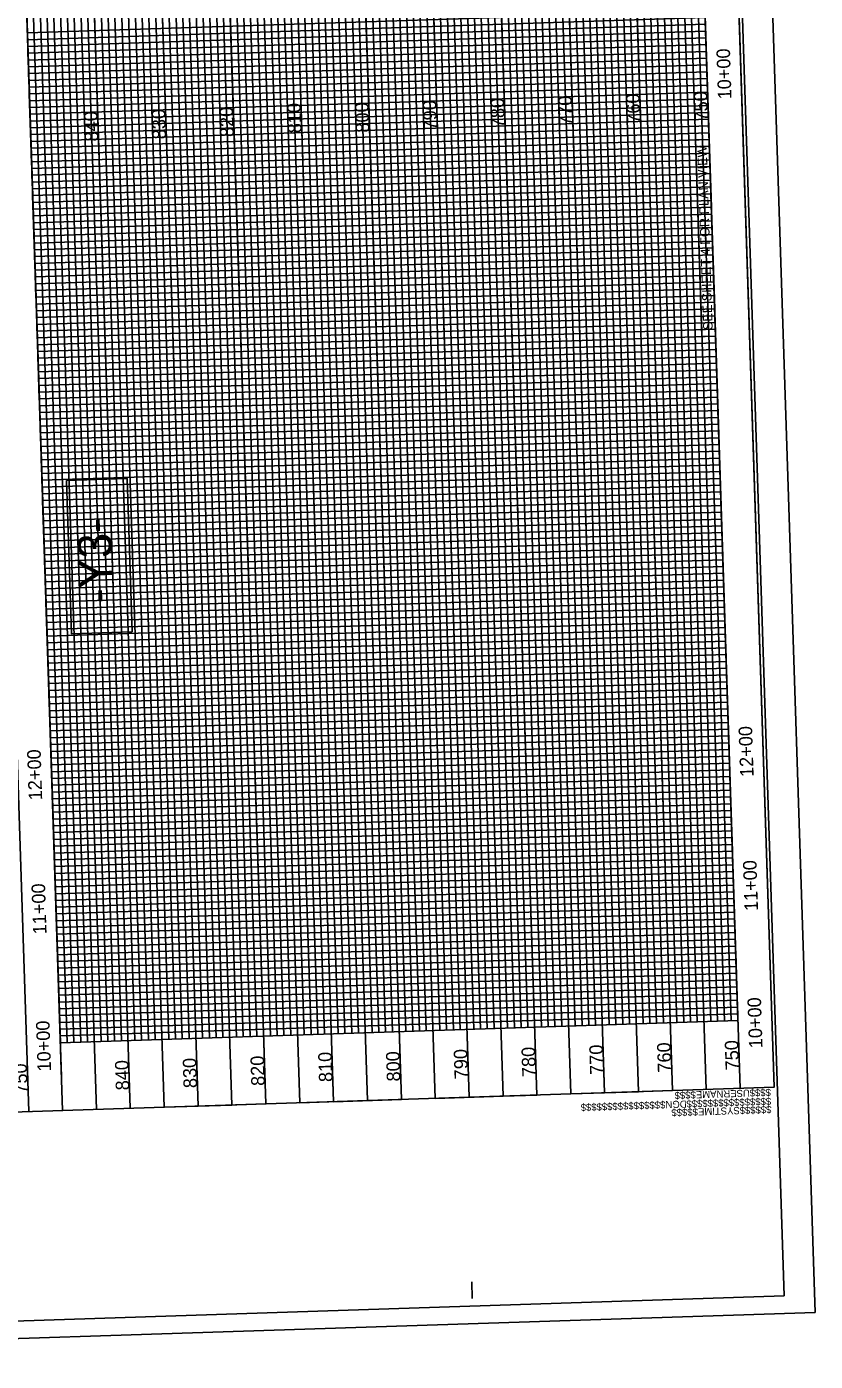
# Model space of a CAD drawing. Extents: x 1627314 to 1628469, y 762309 to 764230.
# Drawn here: x 1627888 to 1628469, y 762309 to 763293 of the extents above; entities that cross this region are included whole.
import ezdxf

# ---------------------------------------------------------------- set-up
doc = ezdxf.new("R2010")
doc.units = 0
for name, color, linetype in [('Exist Vertical Profile Horizontal Axis Label Major', 7, 'Continuous'), ('Exist Vertical Profile Vertical Axis Label', 7, 'Continuous'), ('Prop DSN Text', 7, 'Continuous'), ('Prop Grid Mask', 7, 'Continuous'), ('Sheet Data Field CELL', 7, 'Continuous'), ('Sheet DOT Grid CELL', 7, 'Continuous'), ('Sheet Layout Profile Border Port 2', 7, 'Continuous'), ('Sheet Plot Border Inside CELL', 7, 'Continuous'), ('Sheet Plot Border Outside CELL', 7, 'Continuous'), ('Sheet Profile CELL', 7, 'Continuous'), ('Sheet Profile Grid Major CELL', 7, 'Continuous'), ('Sheet Profile Grid Middle CELL', 7, 'Continuous'), ('Sheet Profile Grid Minor CELL', 7, 'Continuous')]:
    doc.layers.add(name, color=color, linetype=linetype)

msp = doc.modelspace()

# ---------------------------------------------------------------- linework, layer by layer
at = {"layer": 'Prop Grid Mask'}
for points in [[(1627891.16, 763193.83), (1627889.52, 763243.8), (1628389.25, 763260.15), (1628390.89, 763210.18)], [(1628380.89, 763209.85), (1628385.63, 763064.93), (1628395.63, 763065.25), (1628390.89, 763210.18)], [(1627965.43, 762847.15), (1627961.73, 762960.18), (1627917.01, 762958.71), (1627920.71, 762845.69)]]:
    msp.add_lwpolyline(points, close=True, dxfattribs=at)
at = {"layer": 'Sheet DOT Grid CELL'}
for p, q in [((1628163.91, 762502.38), (1628114.87, 764001.46)), ((1628213.88, 762504.01), (1628164.85, 764003.1)), ((1628263.85, 762505.65), (1628214.82, 764004.73)), ((1628313.83, 762507.28), (1628264.79, 764006.37)), ((1628363.8, 762508.92), (1628314.77, 764008)), ((1627914.04, 762494.2), (1627865.01, 763993.29)), ((1627964.01, 762495.84), (1627914.98, 763994.92)), ((1628013.99, 762497.47), (1627964.95, 763996.56)), ((1628063.96, 762499.11), (1628014.93, 763998.19)), ((1628113.93, 762500.74), (1628064.9, 763999.83)), ((1627889.52, 763243.8), (1628389.25, 763260.15)), ((1627891.16, 763193.83), (1628390.89, 763210.18)), ((1627892.79, 763143.86), (1628392.52, 763160.2)), ((1627894.43, 763093.88), (1628394.16, 763110.23)), ((1627896.06, 763043.91), (1628395.79, 763060.26)), ((1627897.69, 762993.94), (1628397.43, 763010.28)), ((1627899.33, 762943.96), (1628399.06, 762960.31)), ((1627900.96, 762893.99), (1628400.7, 762910.34)), ((1627902.6, 762844.02), (1628402.33, 762860.36)), ((1627904.23, 762794.04), (1628403.97, 762810.39)), ((1627905.87, 762744.07), (1628405.6, 762760.42)), ((1627907.5, 762694.1), (1628407.24, 762710.44)), ((1627909.14, 762644.12), (1628408.87, 762660.47)), ((1627910.77, 762594.15), (1628410.5, 762610.5)), ((1627912.41, 762544.18), (1628412.14, 762560.52))]:
    msp.add_line(p, q, dxfattribs=at)
at = {"layer": 'Sheet Layout Profile Border Port 2'}
msp.add_lwpolyline([(1627912.41, 762544.18), (1627866.64, 763943.43), (1628366.37, 763959.78), (1628412.14, 762560.52)], close=True, dxfattribs=at)
at = {"layer": 'Sheet Plot Border Inside CELL'}
msp.add_lwpolyline([(1628446.34, 762357.53), (1628391.86, 764023.14), (1627337.33, 763988.65), (1627391.81, 762323.04)], close=True, dxfattribs=at)
at = {"layer": 'Sheet Plot Border Outside CELL'}
msp.add_lwpolyline([(1628469.21, 762345.27), (1628413.63, 764044.37), (1627314.22, 764008.4), (1627369.79, 762309.31)], close=True, dxfattribs=at)
at = {"layer": 'Sheet Profile CELL'}
for p, q in [((1628364.74, 764009.75), (1628413.77, 762510.55)), ((1628438.76, 762511.37), (1628389.72, 764010.57)), ((1627889.05, 762493.39), (1627840.02, 763992.59)), ((1627914.04, 762494.2), (1627865, 763993.4)), ((1628438.76, 762511.37), (1628438.76, 762511.37)), ((1628438.76, 762511.37), (1628438.76, 762511.37)), ((1628438.76, 762511.37), (1628438.76, 762511.37)), ((1628438.76, 762511.37), (1628438.76, 762511.37)), ((1628438.76, 762511.37), (1628438.76, 762511.37)), ((1628438.76, 762511.37), (1628438.76, 762511.37)), ((1628438.76, 762511.37), (1628438.76, 762511.37)), ((1628216.24, 762355.51), (1628215.83, 762368))]:
    msp.add_line(p, q, dxfattribs=at)
msp.add_lwpolyline([(1627340.28, 763976.24), (1627389.32, 762477.04), (1628438.76, 762511.37), (1628389.72, 764010.57)], close=True, dxfattribs=at)
msp.add_lwpolyline([(1628437.53, 762548.85), (1628437.53, 762548.85)], dxfattribs=at)
at = {"layer": 'Sheet Profile Grid Major CELL'}
for p, q in [((1627891.16, 763193.83), (1627889.52, 763243.8)), ((1627894.43, 763093.88), (1627892.79, 763143.86)), ((1627897.69, 762993.94), (1627896.06, 763043.91)), ((1628413.77, 762510.55), (1628413.77, 762510.55))]:
    msp.add_line(p, q, dxfattribs=at)
for points in [[(1628064.9, 763999.94), (1628113.93, 762500.74), (1628163.91, 762502.38), (1628114.87, 764001.58)], [(1628164.84, 764003.21), (1628213.88, 762504.01), (1628263.85, 762505.65), (1628214.82, 764004.85)], [(1628264.79, 764006.48), (1628313.83, 762507.28), (1628313.83, 762507.28), (1628363.8, 762508.92), (1628314.76, 764008.11)], [(1628364.74, 764009.75), (1628413.77, 762510.55)], [(1627914.98, 763995.04), (1627964.01, 762495.84)], [(1627964.95, 763996.67), (1628013.99, 762497.47), (1628063.96, 762499.11), (1628014.92, 763998.31)], [(1627912.41, 762544.18), (1628412.14, 762560.52), (1628410.5, 762610.5), (1627910.77, 762594.15), (1627909.14, 762644.12), (1628408.87, 762660.47), (1628407.24, 762710.44), (1627907.5, 762694.1), (1627905.87, 762744.07), (1628405.6, 762760.42), (1628403.97, 762810.39), (1627904.23, 762794.04), (1627902.6, 762844.02), (1628402.33, 762860.36), (1628400.7, 762910.34), (1627900.96, 762893.99), (1627899.33, 762943.96), (1628399.06, 762960.31), (1628397.43, 763010.28), (1627897.69, 762993.94), (1627896.06, 763043.91), (1628395.79, 763060.26), (1628394.16, 763110.23), (1627894.43, 763093.88), (1627892.79, 763143.86), (1628392.52, 763160.2), (1628390.89, 763210.18), (1627891.16, 763193.83), (1627889.52, 763243.8), (1628389.25, 763260.15), (1628387.62, 763310.12)]]:
    msp.add_lwpolyline(points, dxfattribs=at)
at = {"layer": 'Sheet Profile Grid Middle CELL'}
for points in [[(1628139.86, 764002.39), (1628188.89, 762503.2), (1628238.87, 762504.83), (1628189.83, 764004.03)], [(1628239.8, 764005.66), (1628288.84, 762506.46), (1628338.81, 762508.1), (1628289.78, 764007.3)], [(1628339.75, 764008.93), (1628388.79, 762509.73)], [(1627939.03, 762495.02), (1627889.99, 763994.22)], [(1627939.96, 763995.85), (1627989, 762496.66), (1628038.97, 762498.29), (1627989.94, 763997.49)], [(1628039.91, 763999.12), (1628088.95, 762499.93), (1628138.92, 762501.56), (1628089.88, 764000.76)], [(1627913.22, 762519.19), (1627911.59, 762569.16), (1628411.32, 762585.51), (1628409.69, 762635.48), (1627909.95, 762619.14), (1627908.32, 762669.11), (1628408.05, 762685.46), (1628406.42, 762735.43), (1627906.69, 762719.08), (1627905.05, 762769.06), (1628404.78, 762785.4), (1628403.15, 762835.38), (1627903.42, 762819.03), (1627901.78, 762869), (1628401.51, 762885.35), (1628399.88, 762935.32), (1627900.15, 762918.98), (1627898.51, 762968.95), (1628398.24, 762985.3), (1628396.61, 763035.27), (1627896.88, 763018.92), (1627895.24, 763068.9), (1628394.98, 763085.24), (1628393.34, 763135.22), (1628393.34, 763135.22), (1627893.61, 763118.87), (1627891.97, 763168.84), (1628391.71, 763185.19), (1628390.07, 763235.16), (1627890.34, 763218.82), (1627888.7, 763268.79), (1628388.44, 763285.14), (1628386.8, 763335.11)]]:
    msp.add_lwpolyline(points, dxfattribs=at)
at = {"layer": 'Sheet Profile Grid Minor CELL'}
for p, q in [((1628167.27, 762552.51), (1628121.5, 763951.77)), ((1628126.5, 763951.93), (1628172.27, 762552.68)), ((1628177.26, 762552.84), (1628131.5, 763952.09)), ((1628136.49, 763952.26), (1628182.26, 762553)), ((1628192.26, 762553.33), (1628146.49, 763952.58)), ((1628151.48, 763952.75), (1628197.25, 762553.5)), ((1628202.25, 762553.66), (1628156.48, 763952.91)), ((1628161.48, 763953.07), (1628207.25, 762553.82)), ((1628217.24, 762554.15), (1628171.47, 763953.4)), ((1628176.47, 763953.56), (1628222.24, 762554.31)), ((1628227.24, 762554.48), (1628181.47, 763953.73)), ((1628186.47, 763953.89), (1628232.24, 762554.64)), ((1628242.23, 762554.97), (1628196.46, 763954.22)), ((1628201.46, 763954.38), (1628247.23, 762555.13)), ((1628252.22, 762555.29), (1628206.46, 763954.55)), ((1628211.45, 763954.71), (1628257.22, 762555.46)), ((1628267.22, 762555.78), (1628221.45, 763955.04)), ((1628226.44, 763955.2), (1628272.21, 762555.95)), ((1628277.21, 762556.11), (1628231.44, 763955.36)), ((1628236.44, 763955.53), (1628282.21, 762556.27)), ((1628292.2, 762556.6), (1628246.43, 763955.85)), ((1628251.43, 763956.02), (1628297.2, 762556.76)), ((1628302.2, 762556.93), (1628256.43, 763956.18)), ((1628261.43, 763956.34), (1628307.2, 762557.09)), ((1628317.19, 762557.42), (1628271.42, 763956.67)), ((1628276.42, 763956.83), (1628322.19, 762557.58)), ((1628327.18, 762557.75), (1628281.42, 763957)), ((1628286.41, 763957.16), (1628332.18, 762557.91)), ((1628342.18, 762558.24), (1628296.41, 763957.49)), ((1628301.4, 763957.65), (1628347.17, 762558.4)), ((1628352.17, 762558.56), (1628306.4, 763957.81)), ((1628311.4, 763957.98), (1628357.17, 762558.73)), ((1628367.16, 762559.05), (1628321.39, 763958.3)), ((1628326.39, 763958.47), (1628372.16, 762559.22)), ((1628377.16, 762559.38), (1628331.39, 763958.63)), ((1628336.39, 763958.8), (1628382.16, 762559.54)), ((1628392.15, 762559.87), (1628346.38, 763959.12)), ((1628351.38, 763959.29), (1628397.15, 762560.03)), ((1628402.14, 762560.2), (1628356.37, 763959.45)), ((1628407.14, 762560.36), (1628361.37, 763959.61)), ((1627917.4, 762544.34), (1627871.63, 763943.59)), ((1627876.63, 763943.76), (1627922.4, 762544.5)), ((1627927.4, 762544.67), (1627881.63, 763943.92)), ((1627886.63, 763944.08), (1627932.4, 762544.83)), ((1627942.39, 762545.16), (1627896.62, 763944.41)), ((1627901.62, 763944.57), (1627947.39, 762545.32)), ((1627952.38, 762545.49), (1627906.62, 763944.74)), ((1627911.61, 763944.9), (1627957.38, 762545.65)), ((1627967.38, 762545.98), (1627921.61, 763945.23)), ((1627926.6, 763945.39), (1627972.37, 762546.14)), ((1627977.37, 762546.3), (1627931.6, 763945.55)), ((1627936.6, 763945.72), (1627982.37, 762546.47)), ((1627992.36, 762546.79), (1627946.59, 763946.05)), ((1627951.59, 763946.21), (1627997.36, 762546.96)), ((1628002.36, 762547.12), (1627956.59, 763946.37)), ((1627961.59, 763946.54), (1628007.36, 762547.28)), ((1628017.35, 762547.61), (1627971.58, 763946.86)), ((1627976.58, 763947.03), (1628022.35, 762547.77)), ((1628027.34, 762547.94), (1627981.58, 763947.19)), ((1627986.57, 763947.35), (1628032.34, 762548.1)), ((1628042.34, 762548.43), (1627996.57, 763947.68)), ((1628001.56, 763947.84), (1628047.33, 762548.59)), ((1628052.33, 762548.75), (1628006.56, 763948.01)), ((1628011.56, 763948.17), (1628057.33, 762548.92)), ((1628067.32, 762549.25), (1628021.55, 763948.5)), ((1628026.55, 763948.66), (1628072.32, 762549.41)), ((1628077.32, 762549.57), (1628031.55, 763948.82)), ((1628036.55, 763948.99), (1628082.32, 762549.74)), ((1628092.31, 762550.06), (1628046.54, 763949.31)), ((1628051.54, 763949.48), (1628097.31, 762550.23)), ((1628102.3, 762550.39), (1628056.54, 763949.64)), ((1628061.53, 763949.8), (1628107.15, 762550.55)), ((1628117.3, 762550.88), (1628071.53, 763950.13)), ((1628076.52, 763950.3), (1628122.29, 762551.04)), ((1628127.29, 762551.21), (1628081.52, 763950.46)), ((1628086.52, 763950.62), (1628132.29, 762551.37)), ((1628142.28, 762551.7), (1628096.51, 763950.95)), ((1628101.51, 763951.11), (1628147.28, 762551.86)), ((1628152.28, 762552.02), (1628106.51, 763951.28)), ((1628111.51, 763951.44), (1628157.28, 762552.19))]:
    msp.add_line(p, q, dxfattribs=at)
for points in [[(1628387.78, 763305.13), (1627888.05, 763288.78), (1627887.72, 763298.77)], [(1627895.08, 763073.89), (1628394.81, 763090.24), (1628394.65, 763095.24), (1627894.92, 763078.89), (1627894.75, 763083.89), (1628394.49, 763100.24), (1628394.32, 763105.23), (1627894.59, 763088.89), (1627894.26, 763098.88), (1628393.99, 763115.23), (1628393.83, 763120.22), (1627894.1, 763103.88), (1627893.94, 763108.88), (1628393.67, 763125.22), (1628393.5, 763130.22), (1627893.77, 763113.87), (1627893.44, 763123.87), (1628393.18, 763140.21), (1628393.01, 763145.21), (1627893.28, 763128.87), (1627893.12, 763133.86), (1628392.85, 763150.21), (1628392.69, 763155.21), (1627892.95, 763138.86), (1627892.63, 763148.85), (1628392.36, 763165.2), (1628392.2, 763170.2), (1627892.46, 763153.85), (1627892.3, 763158.85), (1628392.03, 763175.2), (1628391.87, 763180.19), (1627892.14, 763163.85), (1627891.81, 763173.84), (1628391.54, 763190.19), (1628391.38, 763195.18), (1627891.65, 763178.84), (1627891.48, 763183.84), (1628391.22, 763200.18), (1628391.05, 763205.18), (1627891.32, 763188.83), (1627890.99, 763198.83), (1628390.73, 763215.17), (1628390.73, 763215.17), (1628390.56, 763220.17), (1627890.83, 763203.83), (1627890.67, 763208.82), (1628390.4, 763225.17), (1628390.24, 763230.17), (1627890.5, 763213.82), (1627890.18, 763223.81), (1628389.91, 763240.16), (1628389.74, 763245.16), (1627890.01, 763228.81), (1627889.85, 763233.81), (1628389.58, 763250.16), (1628389.42, 763255.15), (1627889.69, 763238.81), (1627889.36, 763248.8), (1628389.09, 763265.15), (1628388.93, 763270.14), (1627889.19, 763253.8), (1627889.03, 763258.8), (1628388.76, 763275.14), (1628388.6, 763280.14), (1627888.87, 763263.79), (1627888.54, 763273.79), (1628388.27, 763290.13), (1628388.11, 763295.13), (1627888.38, 763278.79), (1627888.21, 763283.78), (1628387.95, 763300.13)], [(1628405.11, 762775.41), (1628404.95, 762780.41), (1627905.21, 762764.06), (1627904.89, 762774.06), (1628404.62, 762790.4), (1628404.46, 762795.4), (1627904.72, 762779.05), (1627904.56, 762784.05), (1628404.29, 762800.4), (1628404.13, 762805.39), (1627904.4, 762789.05), (1627904.07, 762799.04), (1628403.8, 762815.39), (1628403.64, 762820.39), (1627903.91, 762804.04), (1627903.74, 762809.04), (1628403.48, 762825.38), (1628403.31, 762830.38), (1627903.58, 762814.03), (1627903.25, 762824.03), (1628402.99, 762840.37), (1628402.82, 762845.37), (1627903.09, 762829.03), (1627902.93, 762834.02), (1628402.66, 762850.37), (1628402.49, 762855.37), (1627902.76, 762839.02), (1627902.44, 762849.01), (1628402.17, 762865.36), (1628402, 762870.36), (1627902.27, 762854.01), (1627902.11, 762859.01), (1628401.84, 762875.36), (1628401.68, 762880.35), (1627901.94, 762864.01), (1627901.62, 762874), (1628401.35, 762890.35), (1628401.19, 762895.35), (1627901.45, 762879), (1627901.29, 762884), (1628401.02, 762900.34), (1628400.86, 762905.34), (1627901.13, 762888.99), (1627900.8, 762898.99), (1628400.53, 762915.33), (1628400.37, 762920.33), (1627900.64, 762903.99), (1627900.47, 762908.98), (1628400.21, 762925.33), (1628400.04, 762930.33), (1627900.31, 762913.98), (1627899.98, 762923.97), (1628399.72, 762940.32), (1628399.55, 762945.32), (1627899.82, 762928.97), (1627899.66, 762933.97), (1628399.39, 762950.32), (1628399.23, 762955.31), (1627899.49, 762938.97), (1627899.17, 762948.96), (1628398.9, 762965.31), (1628398.74, 762970.31), (1627899, 762953.96), (1627898.84, 762958.96), (1628398.57, 762975.3), (1628398.41, 762980.3), (1627898.68, 762963.95), (1627898.35, 762973.95), (1628398.08, 762990.29), (1628397.92, 762995.29), (1627898.19, 762978.95), (1627898.02, 762983.94), (1628397.75, 763000.29), (1628397.59, 763005.29), (1627897.86, 762988.94), (1627897.53, 762998.93), (1628397.26, 763015.28), (1628397.1, 763020.28), (1627897.37, 763003.93), (1627897.2, 763008.93), (1628396.94, 763025.28), (1628396.77, 763030.27), (1627897.04, 763013.93), (1627896.71, 763023.92), (1628396.45, 763040.27), (1628396.28, 763045.26), (1627896.55, 763028.92), (1627896.39, 763033.92), (1628396.12, 763050.26), (1628395.96, 763055.26), (1627896.22, 763038.91), (1627895.9, 763048.91), (1628395.63, 763065.25), (1628395.47, 763070.25), (1627895.73, 763053.91), (1627895.57, 763058.9), (1628395.3, 763075.25), (1628395.14, 763080.25), (1627895.41, 763063.9), (1627895.08, 763073.89)], [(1627912.41, 762544.18), (1627912.24, 762549.18), (1628411.98, 762565.52), (1628411.81, 762570.52), (1627912.08, 762554.17), (1627911.92, 762559.17), (1628411.65, 762575.52), (1628411.49, 762580.51), (1627911.75, 762564.17), (1627911.43, 762574.16), (1628411.16, 762590.51), (1628410.99, 762595.51), (1627911.26, 762579.16), (1627911.1, 762584.16), (1628410.83, 762600.5), (1628410.67, 762605.5), (1628410.34, 762615.49), (1628410.18, 762620.49), (1627910.44, 762604.15), (1627910.28, 762609.14), (1628410.01, 762625.49), (1628409.85, 762630.49), (1627910.12, 762614.14), (1627909.79, 762624.14), (1628409.52, 762640.48), (1628409.36, 762645.48), (1627909.63, 762629.13), (1627909.46, 762634.13), (1628409.2, 762650.48), (1628409.03, 762655.47), (1627909.3, 762639.13), (1627908.97, 762649.12), (1628408.71, 762665.47), (1628408.54, 762670.47), (1627908.81, 762654.12), (1627908.65, 762659.12), (1628408.38, 762675.46), (1628408.22, 762680.46), (1627908.48, 762664.11), (1627908.16, 762674.11), (1628407.89, 762690.45), (1628407.73, 762695.45), (1627907.99, 762679.11), (1627907.83, 762684.1), (1628407.56, 762700.45), (1628407.4, 762705.45), (1627907.67, 762689.1), (1627907.34, 762699.1), (1628407.07, 762715.44), (1628406.91, 762720.44), (1627907.18, 762704.09), (1627907.01, 762709.09), (1628406.74, 762725.44), (1628406.58, 762730.43), (1627906.85, 762714.09), (1627906.52, 762724.08), (1628406.25, 762740.43), (1628406.09, 762745.43), (1627906.36, 762729.08), (1627906.19, 762734.08), (1628405.93, 762750.42), (1628405.76, 762755.42), (1627906.03, 762739.07), (1627905.7, 762749.07), (1628405.44, 762765.41), (1628405.27, 762770.41), (1627905.54, 762754.07), (1627905.38, 762759.06), (1628405.11, 762775.41)], [(1628410.67, 762605.5), (1627910.94, 762589.15), (1627910.61, 762599.15), (1628410.34, 762615.49)]]:
    msp.add_lwpolyline(points, dxfattribs=at)

# ---------------------------------------------------------------- texts
at = {"layer": 'Exist Vertical Profile Horizontal Axis Label Major'}
for s, p in [('10+00', (1628407.43, 763239.93)), ('12+00', (1628423.77, 762740.31)), ('12+00', (1627899.05, 762723.15)), ('11+00', (1628427, 762641.45)), ('11+00', (1627902.28, 762624.28)), ('10+00', (1628430.31, 762540.3)), ('10+00', (1627905.59, 762523.14))]:
    msp.add_text(s, height=10, rotation=91.87347, dxfattribs=at).set_placement(p)
at = {"layer": 'Exist Vertical Profile Vertical Axis Label'}
for s, p in [('760', (1628340.23, 763221.96)), ('750', (1628390.2, 763223.59)), ('820', (1628040.39, 763212.15)), ('810', (1628090.32, 763214.98)), ('800', (1628140.33, 763215.42)), ('790', (1628190.31, 763217.05)), ('780', (1628240.28, 763218.69)), ('770', (1628290.25, 763220.32)), ('840', (1627940.44, 763208.88)), ('830', (1627990.41, 763210.52)), ('750', (1628413.08, 762523.97)), ('810', (1628113.21, 762515.36)), ('800', (1628163.22, 762515.79)), ('790', (1628213.19, 762517.43)), ('780', (1628263.16, 762519.06)), ('770', (1628313.14, 762520.7)), ('760', (1628363.11, 762522.33)), ('750', (1627888.37, 762506.8)), ('840', (1627963.33, 762509.26)), ('830', (1628013.3, 762510.89)), ('820', (1628063.27, 762512.53))]:
    msp.add_text(s, height=10, rotation=91.87347, dxfattribs=at).set_placement(p)
at = {"layer": 'Prop DSN Text'}
msp.add_text('SEE SHEET 4 FOR PLAN VIEW', height=7, rotation=91.87347, dxfattribs=at).set_placement((1628393.53, 763069.77))
at = {"layer": 'Sheet Data Field CELL'}
msp.add_text('-Y3-', height=25, rotation=91.87347, dxfattribs=at).set_placement((1627951.67, 762868.44))
at = {"layer": 'Sheet Profile CELL'}
for s, p in [('$$$$USERNAME$$$$', (1628436.41, 762510.23)), ('$$$$$$$$$$$$$$$$DGN$$$$$$$$$$$$$$$$', (1628436.64, 762503.66)), ('$$$$$$SYSTIME$$$$$', (1628436.83, 762497.61))]:
    msp.add_text(s, height=5.25, rotation=181.87347, dxfattribs=at).set_placement(p)

doc.saveas('drawing.dxf')
